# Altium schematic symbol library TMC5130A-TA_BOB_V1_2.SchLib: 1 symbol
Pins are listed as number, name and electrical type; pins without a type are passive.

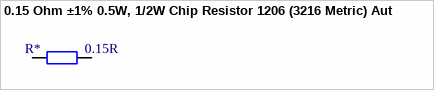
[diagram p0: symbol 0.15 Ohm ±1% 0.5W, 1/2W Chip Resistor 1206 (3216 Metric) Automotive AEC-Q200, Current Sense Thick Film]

## 0.15 Ohm ±1% 0.5W, 1/2W Chip Resistor 1206 (3216 Metric) Automotive AEC-Q200, Current Sense Thick Film
designator R*, comment Resistance: 0.15R  (hidden comment: 0.15R / 0.5W / 1%)
0.15 Ohm ±1% 0.5W, 1/2W Chip Resistor 1206 (3216 Metric) Automotive AEC-Q200, Current Sense Thick Film; MPN: ERJ-8BSFR15V; Temp coefficient: *ppm; MF: Panasonic
footprint R0402 (0402 resistor)
footprint R0603 (0603 resistor)
footprint R0805 (0805 resistor)
footprint R1206 (1206 resistor)
footprint R2512 (2512 resistor)
footprint R0201 (0201 resistor)
footprint R1210 (1210 resistor)
footprint R1812 (1812 resistor)
footprint R2010 (2010 resistor)
footprint R2512 (2512 resistor)
pins: 1, 2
